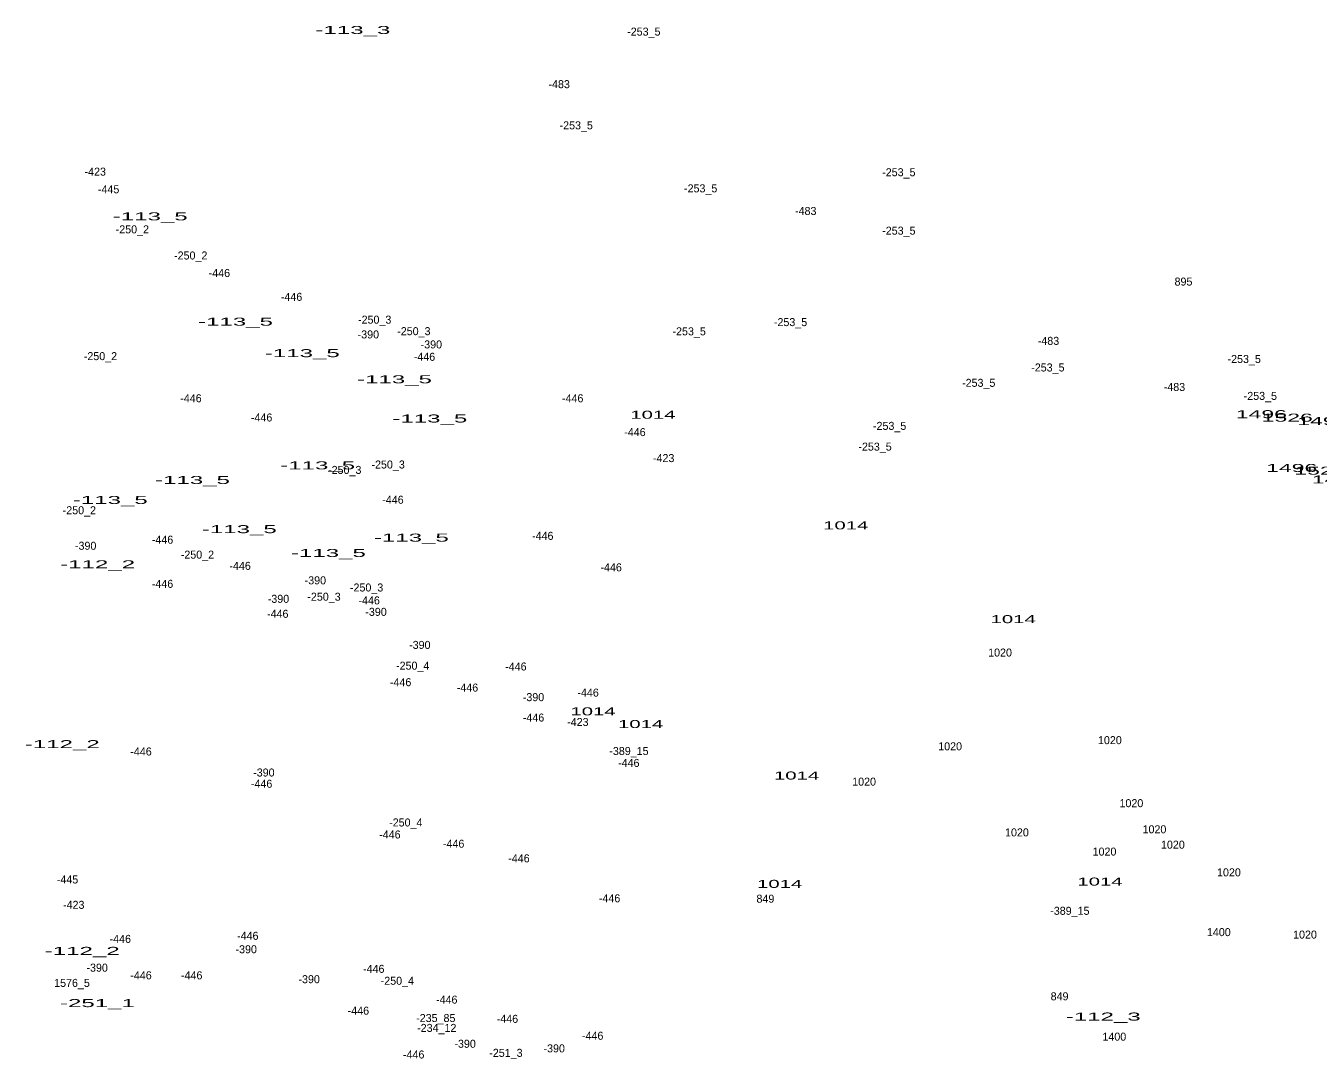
# Model space of a CAD drawing. Extents: x -660434 to -656144, y -997850 to -994016.
# Drawn here: x -660120 to -659474, y -995040 to -994524 of the extents above; entities that cross this region are included whole.
import ezdxf
from ezdxf.enums import TextEntityAlignment as Align

# ---------------------------------------------------------------- set-up
doc = ezdxf.new("R2010")
doc.units = 0
doc.header["$LTSCALE"] = 1.6
doc.layers.add('24', color=7, linetype='Continuous')

msp = doc.modelspace()

# ---------------------------------------------------------------- texts
at = {"layer": '24'}
for s, width, p in [('-113_3', 2.25, (-659956.617, -994527.8)), ('-113_5', 2.25, (-660057.927, -994620.97)), ('-113_5', 2.25, (-660015.307, -994673.6)), ('-113_5', 2.25, (-659981.897, -994689.35)), ('-113_5', 2.25, (-659935.817, -994702.41)), ('-113_5', 2.25, (-659918.147, -994722.01)), ('1014', 1.9, (-659806.616, -994720.12)), ('1496', 2.15, (-659502.443, -994719.85)), ('1526', 2.15, (-659489.493, -994721.58)), ('1496', 2.15, (-659471.723, -994723.3)), ('-113_5', 2.25, (-659974.217, -994745.44)), ('1496', 2.15, (-659487.283, -994746.73)), ('1526', 2.15, (-659473.173, -994748.08)), ('-113_5', 2.25, (-660036.807, -994752.74)), ('1496', 2.15, (-659464.433, -994752.5)), ('-113_5', 2.25, (-660077.897, -994762.73)), ('-113_5', 2.25, (-660013.387, -994777.32)), ('1014', 1.9, (-659710.226, -994775.43)), ('-113_5', 2.25, (-659927.367, -994781.55)), ('-113_5', 2.25, (-659968.847, -994789.23)), ('-112_2', 2.25, (-660084.237, -994794.9)), ('1014', 1.9, (-659626.516, -994822.3)), ('1014', 1.9, (-659836.566, -994868.4)), ('1014', 1.9, (-659812.756, -994874.74)), ('-112_2', 2.25, (-660101.907, -994884.79)), ('1014', 1.9, (-659734.806, -994900.48)), ('1014', 1.9, (-659743.256, -994954.64)), ('1014', 1.9, (-659583.116, -994953.49)), ('-112_2', 2.25, (-660091.917, -994988.13)), ('-251_1', 2.25, (-660084.307, -995014.22)), ('-112_3', 2.25, (-659581.487, -995020.96))]:
    msp.add_text(s, height=4, dxfattribs=dict(at, width=width)).set_placement(p, align=Align.CENTER)
for s, p in [('-253_5', (-659811.162, -994528.62)), ('-483', (-659853.479, -994554.89)), ('-253_5', (-659844.952, -994575.47)), ('-423', (-660085.409, -994598.62)), ('-253_5', (-659683.672, -994598.92)), ('-445', (-660078.723, -994607.43)), ('-253_5', (-659782.742, -994606.97)), ('-483', (-659730.219, -994618.27)), ('-250_2', (-660066.876, -994627.46)), ('-253_5', (-659683.672, -994628.12)), ('-250_2', (-660037.686, -994640.52)), ('-446', (-660023.359, -994649.29)), ('895', (-659541.373, -994653.57)), ('-446', (-659987.269, -994661.2)), ('-250_3', (-659945.716, -994672.6)), ('-253_5', (-659737.812, -994673.83)), ('-390', (-659948.884, -994679.98)), ('-250_3', (-659926.126, -994678.36)), ('-253_5', (-659788.502, -994678.44)), ('-483', (-659608.869, -994683.2)), ('-390', (-659917.394, -994684.98)), ('-250_2', (-660082.806, -994690.84)), ('-446', (-659920.829, -994691.15)), ('-253_5', (-659609.172, -994696.5)), ('-253_5', (-659511.022, -994692.27)), ('-253_5', (-659643.732, -994704.18)), ('-483', (-659545.889, -994706.25)), ('-446', (-660037.569, -994711.9)), ('-446', (-659846.719, -994711.91)), ('-253_5', (-659502.952, -994710.71)), ('-446', (-660002.239, -994721.5)), ('-446', (-659815.609, -994728.81)), ('-253_5', (-659688.282, -994725.7)), ('-423', (-659801.249, -994741.8)), ('-253_5', (-659695.572, -994736.07)), ('-250_3', (-659960.686, -994747.7)), ('-250_3', (-659938.996, -994745.01)), ('-250_2', (-660093.366, -994767.87)), ('-446', (-659936.579, -994762.61)), ('-446', (-659861.689, -994780.66)), ('-390', (-660090.204, -994785.62)), ('-446', (-660051.779, -994782.59)), ('-250_2', (-660034.326, -994790.05)), ('-446', (-660012.999, -994795.66)), ('-446', (-659827.509, -994796.41)), ('-446', (-660051.779, -994804.66)), ('-390', (-659975.384, -994802.91)), ('-250_3', (-659949.746, -994806.48)), ('-390', (-659993.814, -994812.14)), ('-250_3', (-659971.056, -994811.09)), ('-446', (-659948.479, -994812.93)), ('-390', (-659945.044, -994818.66)), ('-446', (-659994.179, -994819.64)), ('-390', (-659923.154, -994835.18)), ('1020', (-659633.078, -994839)), ('-250_4', (-659926.711, -994845.56)), ('-446', (-659875.129, -994845.98)), ('-446', (-659932.739, -994853.83)), ('-446', (-659899.329, -994856.52)), ('-390', (-659866.324, -994861.3)), ('-446', (-659839.029, -994859.04)), ('-446', (-659866.299, -994871.5)), ('-423', (-659844.139, -994873.72)), ('1020', (-659578.168, -994882.79)), ('-446', (-660062.529, -994888.46)), ('-389_15', (-659818.601, -994888.22)), ('1020', (-659658.038, -994885.87)), ('-446', (-659818.679, -994894.17)), ('-390', (-660001.114, -994898.96)), ('1020', (-659701.048, -994903.54)), ('-446', (-660002.249, -994904.59)), ('1020', (-659567.418, -994914.29)), ('-250_4', (-659930.161, -994923.93)), ('1020', (-659624.628, -994928.89)), ('1020', (-659555.888, -994927.35)), ('-446', (-659938.109, -994929.95)), ('-446', (-659906.239, -994934.56)), ('1020', (-659546.678, -994935.04)), ('-446', (-659873.599, -994941.86)), ('1020', (-659580.858, -994938.49)), ('-445', (-660099.263, -994952.42)), ('1020', (-659518.648, -994948.87)), ('-423', (-660096.159, -994965.1)), ('-446', (-659828.279, -994961.84)), ('849', (-659750.387, -994962.04)), ('-389_15', (-659598.181, -994968.09)), ('-446', (-660009.159, -994980.6)), ('1400', (-659523.712, -994978.75)), ('1020', (-659480.628, -994979.98)), ('-446', (-660072.899, -994982.14)), ('-390', (-660009.944, -994987.31)), ('-390', (-660084.454, -994996.52)), ('-446', (-660062.529, -995000.34)), ('-446', (-660037.189, -995000.34)), ('-446', (-659946.179, -994997.12)), ('1576_5', (-660097.04, -995004.13)), ('-390', (-659978.464, -995002.28)), ('-250_4', (-659934.391, -995003.06)), ('-446', (-659909.689, -995012.49)), ('849', (-659603.317, -995010.83)), ('-446', (-659953.859, -995018.01)), ('-235_85', (-659915.171, -995021.7)), ('-446', (-659879.359, -995022.09)), ('-234_12', (-659914.679, -995026.63)), ('-446', (-659836.729, -995030.54)), ('1400', (-659575.942, -995031)), ('-390', (-659900.504, -995034.55)), ('-251_3', (-659880.106, -995039.09)), ('-390', (-659855.964, -995036.86)), ('-446', (-659926.209, -995039.91))]:
    msp.add_text(s, height=4, dxfattribs=at).set_placement(p, align=Align.CENTER)

doc.saveas('drawing.dxf')
